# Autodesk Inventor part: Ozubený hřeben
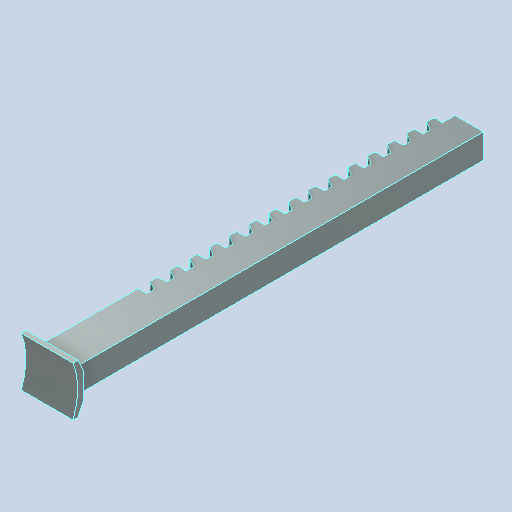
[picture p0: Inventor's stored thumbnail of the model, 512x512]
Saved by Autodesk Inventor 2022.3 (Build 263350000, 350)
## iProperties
Created: 2022-03
Part Number: Ozubený hřeben
Material: Všeobecné
Document SubType Name: Modeling
Designer: Hra42
Density: 1 g/cm^3
Appearance: Výchozí
Author: Hra42
Sending System: SolidWorks 2012
Last Author: Hra42
Last Saved: 2025-11-13
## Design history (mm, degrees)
feature "Importovaný1"
node "Těleso1"
